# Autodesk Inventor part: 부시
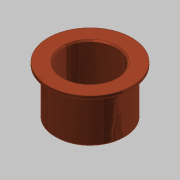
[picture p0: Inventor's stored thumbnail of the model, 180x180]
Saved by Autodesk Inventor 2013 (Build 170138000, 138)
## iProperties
Created: 2015-10
Part Number: 부시
Document SubType Name: Modeling
Designer: mdu
Density: 7.86 g/cm^3
Material: 강철, 연강
Mass: 246.97 g
Surface Area: 129.264 cm^2
Volume: 31.4212 cm^3
Author: mdu
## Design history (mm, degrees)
sketch "스케치1"
  geometry: C1 r 31 at (0, 0) reference; C2 r 25 at (0, 0) reference; C3 r 30 at (0, 0) reference; 1 further point
  node "참조1"
  node "참조2"
  node "참조4"
extrude "돌출1" new body sketch "스케치1" distance "d0" = 3; taper "d1" = 0 deg
extrude "돌출2" join sketch "스케치1" distance "d2" = 35; taper "d3" = 0 deg
chamfer "모따기1" distance "d6" = 1; stored, may be unused: second distance "d7" = 2, angle "d8" = 45 deg
sketch "스케치3"
  geometry: C1 r 19 at (0, 0); 1 further point
  constraints: 1 centre point, 1 coincident
  dimensions: "d13" = 38 diameter of C1
extrude "돌출4" cut sketch "스케치3" stored distance "d14" = 10; taper "d15" = 0 deg
chamfer "모따기3" distance "d16" = 1; stored, may be unused: second distance "d17" = 2, angle "d18" = 45 deg
node "솔리드1"
